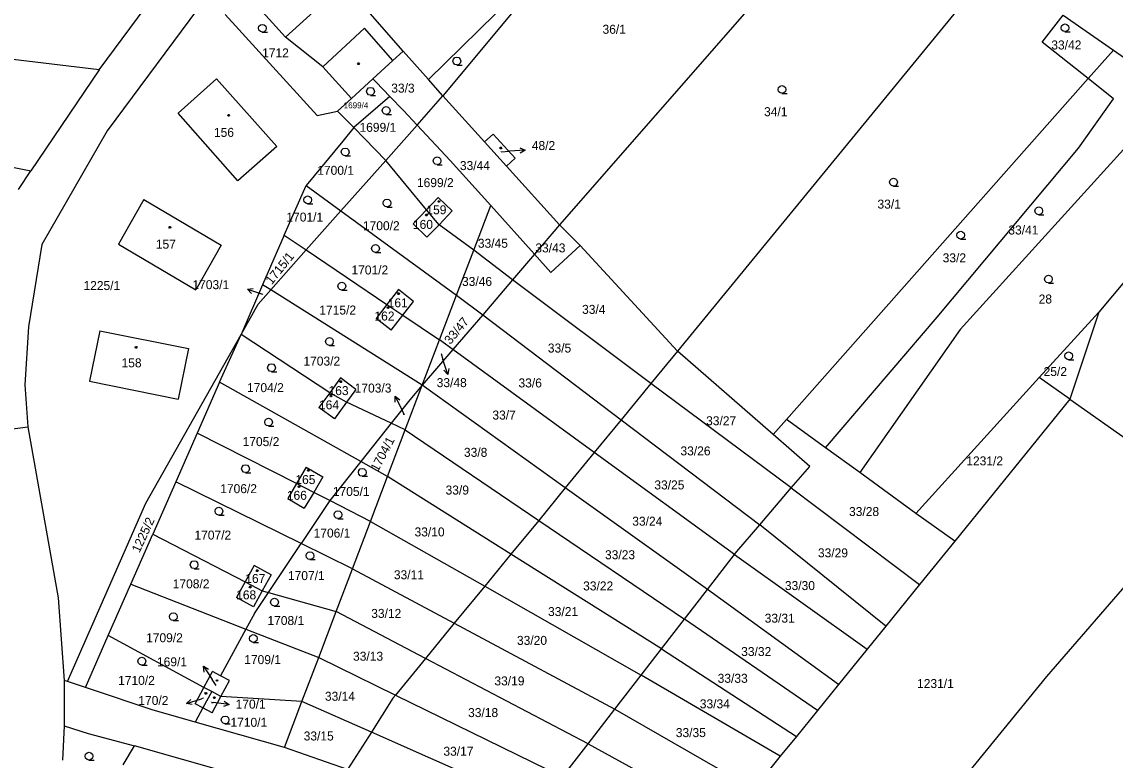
# Model space of a CAD drawing. Extents: x -802857 to -799647, y -1020285 to -1015884.
# Drawn here: x -801708.7 to -801501.8, y -1017921.9 to -1017782.1 of the extents above; entities that cross this region are included whole.
import ezdxf

# ---------------------------------------------------------------- set-up
doc = ezdxf.new("R2010")
doc.units = 0
for name, color, linetype in [('Default', 7, 'Continuous'), ('KN_HRANICE', 7, 'Continuous'), ('KN_KULTURY', 7, 'Continuous'), ('KN_PARCELY', 7, 'Continuous'), ('KN_SLUCKY', 7, 'Continuous')]:
    doc.layers.add(name, color=color, linetype=linetype)

# ---------------------------------------------------------------- blocks, each defined once
blk = doc.blocks.new('304')
at = {"layer": 'Default'}
blk.add_lwpolyline([(0, 0), (-0.38, 0.1), (-0.65, 0.37), (-0.75, 0.74), (-0.65, 1.11), (-0.38, 1.38), (-0.01, 1.48), (0.36, 1.38), (0.63, 1.11), (0.73, 0.73), (0.63, 0.35), (0.36, 0.08), (-0.02, -0.02), (0.98, -0.02)], dxfattribs=at)
blk = doc.blocks.new('10292')
at = {"layer": 'Default'}
blk.add_line((0, 3), (0, 0), dxfattribs=at)
blk.add_lwpolyline([(-0.5, 2), (0, 3), (0.5, 2)], dxfattribs=at)
blk = doc.blocks.new('402')
at = {"layer": 'Default'}
blk.add_lwpolyline([(0.09, 0.15), (0.18, 0), (0.09, -0.15), (-0.09, -0.15), (-0.18, 0), (-0.09, 0.15), (0.09, 0.15)], dxfattribs=at)

msp = doc.modelspace()

# ---------------------------------------------------------------- linework, layer by layer
at = {"layer": 'KN_HRANICE'}
for p, q in [((-801587.49, -1017746.18), (-801629.02, -1017796.14)), ((-801636.53, -1017787.69), (-801656.2, -1017765.17)), ((-801665.9, -1017766.77), (-801692.56, -1017802.78)), ((-801606.88, -1017768.59), (-801631.76, -1017793.06)), ((-801560.55, -1017767.41), (-801606.93, -1017820.56)), ((-801694.1, -1017791.18), (-801681, -1017773.54)), ((-801526.7, -1017773.73), (-801584.65, -1017844.45)), ((-801658.84, -1017785), (-801667.4, -1017775.47)), ((-801670.22, -1017780.7), (-801652.82, -1017799.83)), ((-801515.62, -1017785.98), (-801511.62, -1017780.82)), ((-801511.62, -1017780.82), (-801502.15, -1017787.45)), ((-801651.72, -1017790.61), (-801658.84, -1017785)), ((-801506.94, -1017792.87), (-801515.62, -1017785.98)), ((-801694.1, -1017791.18), (-801711.96, -1017789.03)), ((-801636.53, -1017787.69), (-801638.49, -1017789.43)), ((-801631.76, -1017793.06), (-801636.53, -1017787.69)), ((-801506.94, -1017792.87), (-801502.15, -1017787.45)), ((-801502.15, -1017787.45), (-801490.56, -1017795.57)), ((-801694.1, -1017791.18), (-801707.01, -1017810.3)), ((-801651.72, -1017790.61), (-801646.32, -1017796.61)), ((-801638.49, -1017789.43), (-801642.29, -1017792.91)), ((-801679.14, -1017799.41), (-801671.86, -1017792.92)), ((-801671.86, -1017792.92), (-801660.48, -1017805.72)), ((-801642.29, -1017792.91), (-801646.32, -1017796.61)), ((-801641.68, -1017793.54), (-801642.29, -1017792.91)), ((-801629.02, -1017796.14), (-801631.76, -1017793.06)), ((-801563.98, -1017857.43), (-801506.94, -1017792.87)), ((-801502.12, -1017796.69), (-801506.94, -1017792.87)), ((-801641.68, -1017793.54), (-801639.09, -1017796.22)), ((-801531.17, -1017840.39), (-801490.56, -1017795.57)), ((-801646.32, -1017796.61), (-801648.95, -1017799.02)), ((-801639.09, -1017796.22), (-801645.9, -1017802.13)), ((-801639.09, -1017796.22), (-801636.48, -1017798.92)), ((-801633.91, -1017801.66), (-801629.02, -1017796.14)), ((-801629.02, -1017796.14), (-801621.14, -1017804.85)), ((-801508.75, -1017806.02), (-801502.12, -1017796.69)), ((-801667.86, -1017812.23), (-801679.14, -1017799.41)), ((-801652.82, -1017799.83), (-801648.95, -1017799.02)), ((-801645.9, -1017802.13), (-801648.95, -1017799.02)), ((-801636.48, -1017798.92), (-801633.91, -1017801.66)), ((-801754.22, -1017801.07), (-801707.01, -1017810.3)), ((-801639.83, -1017808.34), (-801633.91, -1017801.66)), ((-801633.91, -1017801.66), (-801627.63, -1017808.36)), ((-801692.56, -1017802.78), (-801704.91, -1017824.25)), ((-801645.9, -1017802.13), (-801647.97, -1017804.68)), ((-801645.9, -1017802.13), (-801639.83, -1017808.34)), ((-801621.14, -1017804.85), (-801619.52, -1017803.38)), ((-801619.52, -1017803.38), (-801615.33, -1017807.93)), ((-801660.48, -1017805.72), (-801667.86, -1017812.23)), ((-801647.97, -1017804.68), (-801654.93, -1017813.11)), ((-801621.14, -1017804.85), (-801616.99, -1017809.44)), ((-801477.67, -1017804.6), (-801504.93, -1017837.07)), ((-801616.99, -1017809.44), (-801615.33, -1017807.93)), ((-801535.49, -1017838.02), (-801508.75, -1017806.02)), ((-801648.32, -1017817.92), (-801639.83, -1017808.34)), ((-801632.1, -1017817.7), (-801639.83, -1017808.34)), ((-801627.63, -1017808.36), (-801619.98, -1017816.88)), ((-801616.99, -1017809.44), (-801606.93, -1017820.56)), ((-801709.32, -1017813.86), (-801707.01, -1017810.3)), ((-801659.05, -1017822.48), (-801654.93, -1017813.11)), ((-801654.93, -1017813.11), (-801648.32, -1017817.92)), ((-801685.6, -1017815.77), (-801690.43, -1017824.24)), ((-801685.6, -1017815.77), (-801670.98, -1017824.37)), ((-801632.1, -1017817.7), (-801629.89, -1017815.39)), ((-801627.26, -1017817.92), (-801629.89, -1017815.39)), ((-801654.87, -1017825.31), (-801648.32, -1017817.92)), ((-801648.32, -1017817.92), (-801626.43, -1017833.85)), ((-801634.67, -1017820.37), (-801632.1, -1017817.7)), ((-801629.76, -1017820.53), (-801632.1, -1017817.7)), ((-801627.26, -1017817.92), (-801629.76, -1017820.53)), ((-801623.2, -1017825.34), (-801619.98, -1017816.88)), ((-801619.98, -1017816.88), (-801611.69, -1017826.12)), ((-801632.04, -1017822.9), (-801634.67, -1017820.37)), ((-801629.76, -1017820.53), (-801632.04, -1017822.9)), ((-801623.2, -1017825.34), (-801629.76, -1017820.53)), ((-801606.93, -1017820.56), (-801611.69, -1017826.12)), ((-801603.03, -1017824.46), (-801606.93, -1017820.56)), ((-801704.91, -1017824.25), (-801707.43, -1017839.85)), ((-801690.43, -1017824.24), (-801675.81, -1017832.84)), ((-801670.98, -1017824.37), (-801675.81, -1017832.84)), ((-801659.05, -1017822.48), (-801663.18, -1017831.89)), ((-801659.05, -1017822.48), (-801654.87, -1017825.31)), ((-801608.61, -1017829.56), (-801603.03, -1017824.46)), ((-801603.03, -1017824.46), (-801584.65, -1017844.45)), ((-801661.59, -1017832.89), (-801654.87, -1017825.31)), ((-801654.87, -1017825.31), (-801639.62, -1017835.62)), ((-801626.43, -1017833.85), (-801623.2, -1017825.34)), ((-801615.84, -1017830.97), (-801623.2, -1017825.34)), ((-801611.69, -1017826.12), (-801615.84, -1017830.97)), ((-801611.69, -1017826.12), (-801608.61, -1017829.56)), ((-801663.18, -1017831.89), (-801667.22, -1017841.33)), ((-801661.59, -1017832.89), (-801663.18, -1017831.89)), ((-801637.45, -1017832.82), (-801639.62, -1017835.62)), ((-801634.57, -1017835.06), (-801637.45, -1017832.82)), ((-801615.84, -1017830.97), (-801621.5, -1017837.59)), ((-801589.67, -1017850.59), (-801615.84, -1017830.97)), ((-801663.99, -1017835.6), (-801661.59, -1017832.89)), ((-801632.93, -1017850.94), (-801661.59, -1017832.89)), ((-801629.66, -1017842.35), (-801626.43, -1017833.85)), ((-801626.43, -1017833.85), (-801621.5, -1017837.59)), ((-801667.22, -1017841.33), (-801663.99, -1017835.6)), ((-801639.62, -1017835.62), (-801641.68, -1017838.27)), ((-801639.62, -1017835.62), (-801636.59, -1017837.67)), ((-801636.59, -1017837.67), (-801634.57, -1017835.06)), ((-801638.8, -1017840.51), (-801641.68, -1017838.27)), ((-801638.8, -1017840.51), (-801636.59, -1017837.67)), ((-801636.59, -1017837.67), (-801629.66, -1017842.35)), ((-801621.5, -1017837.59), (-801627.15, -1017844.18)), ((-801621.5, -1017837.59), (-801595.3, -1017857.46)), ((-801556.62, -1017862.76), (-801535.49, -1017838.02)), ((-801504.93, -1017837.07), (-801516.16, -1017849.45)), ((-801504.93, -1017837.07), (-801510.41, -1017853.59)), ((-801707.43, -1017839.85), (-801708.15, -1017850.85)), ((-801693.95, -1017840.61), (-801695.91, -1017850.17)), ((-801693.95, -1017840.61), (-801677.18, -1017843.99)), ((-801531.17, -1017840.39), (-801550.13, -1017867.47)), ((-801685.23, -1017873.24), (-801667.22, -1017841.33)), ((-801671.28, -1017850.32), (-801667.22, -1017841.33)), ((-801650.45, -1017852.35), (-801667.22, -1017841.33)), ((-801632.93, -1017850.94), (-801629.66, -1017842.35)), ((-801627.15, -1017844.18), (-801629.66, -1017842.35)), ((-801677.18, -1017843.99), (-801679.14, -1017853.55)), ((-801627.15, -1017844.18), (-801632.93, -1017850.94)), ((-801600.38, -1017863.66), (-801627.15, -1017844.18)), ((-801584.65, -1017844.45), (-801589.67, -1017850.59)), ((-801566.54, -1017860.25), (-801584.65, -1017844.45)), ((-801708.15, -1017850.85), (-801707.54, -1017858.79)), ((-801695.91, -1017850.17), (-801679.14, -1017853.55)), ((-801671.28, -1017850.32), (-801675.52, -1017859.98)), ((-801644.53, -1017865.36), (-801671.28, -1017850.32)), ((-801648.43, -1017849.55), (-801650.45, -1017852.35)), ((-801645.48, -1017851.7), (-801648.43, -1017849.55)), ((-801636.14, -1017859.39), (-801632.93, -1017850.94)), ((-801632.93, -1017850.94), (-801635.29, -1017853.7)), ((-801605.86, -1017870.35), (-801632.93, -1017850.94)), ((-801589.67, -1017850.59), (-801595.3, -1017857.46)), ((-801563.11, -1017870.36), (-801589.67, -1017850.59)), ((-801516.16, -1017849.45), (-801539.5, -1017875.18)), ((-801510.41, -1017853.59), (-801516.16, -1017849.45)), ((-801650.45, -1017852.35), (-801652.49, -1017855.13)), ((-801647.25, -1017854.13), (-801650.45, -1017852.35)), ((-801645.48, -1017851.7), (-801647.25, -1017854.13)), ((-801649.54, -1017857.28), (-801652.49, -1017855.13)), ((-801647.25, -1017854.13), (-801649.54, -1017857.28)), ((-801638.8, -1017858.13), (-801647.25, -1017854.13)), ((-801635.29, -1017853.7), (-801638.8, -1017858.13)), ((-801510.41, -1017853.59), (-801532.16, -1017880.43)), ((-801510.41, -1017853.59), (-801498.22, -1017862.16)), ((-801595.3, -1017857.46), (-801600.38, -1017863.66)), ((-801595.3, -1017857.46), (-801569.08, -1017877.35)), ((-801563.98, -1017857.43), (-801566.54, -1017860.25)), ((-801556.62, -1017862.76), (-801563.98, -1017857.43)), ((-801717.29, -1017860.13), (-801707.54, -1017858.79)), ((-801707.54, -1017858.79), (-801701.82, -1017891.2)), ((-801638.8, -1017858.13), (-801644.53, -1017865.36)), ((-801639.49, -1017868.19), (-801636.14, -1017859.39)), ((-801636.14, -1017859.39), (-801638.8, -1017858.13)), ((-801636.14, -1017859.39), (-801610.9, -1017876.51)), ((-801675.52, -1017859.98), (-801679.59, -1017869.24)), ((-801656.73, -1017869.56), (-801675.52, -1017859.98)), ((-801559.61, -1017866.3), (-801566.54, -1017860.25)), ((-801600.38, -1017863.66), (-801605.86, -1017870.35)), ((-801573.84, -1017882.97), (-801600.38, -1017863.66)), ((-801550.13, -1017867.47), (-801556.62, -1017862.76)), ((-801644.53, -1017865.36), (-801650.41, -1017872.78)), ((-801639.49, -1017868.19), (-801644.53, -1017865.36)), ((-801654.89, -1017866.43), (-801656.73, -1017869.56)), ((-801654.89, -1017866.43), (-801651.74, -1017868.29)), ((-801563.11, -1017870.36), (-801559.61, -1017866.3)), ((-801539.5, -1017875.18), (-801550.13, -1017867.47)), ((-801679.59, -1017869.24), (-801683.94, -1017879.14)), ((-801655.86, -1017880.92), (-801679.59, -1017869.24)), ((-801656.73, -1017869.56), (-801658.39, -1017872.37)), ((-801653.47, -1017871.22), (-801656.73, -1017869.56)), ((-801651.74, -1017868.29), (-801653.47, -1017871.22)), ((-801642.73, -1017876.71), (-801639.49, -1017868.19)), ((-801616.14, -1017882.9), (-801639.49, -1017868.19)), ((-801514.75, -1017906.05), (-801482.86, -1017869.28)), ((-801653.47, -1017871.22), (-801655.25, -1017874.23)), ((-801650.41, -1017872.78), (-801653.47, -1017871.22)), ((-801605.86, -1017870.35), (-801610.9, -1017876.51)), ((-801578.98, -1017889.62), (-801605.86, -1017870.35)), ((-801569.08, -1017877.35), (-801563.11, -1017870.36)), ((-801563.11, -1017870.36), (-801538.82, -1017888.65)), ((-801700.05, -1017907.03), (-801685.23, -1017873.24)), ((-801658.39, -1017872.37), (-801655.25, -1017874.23)), ((-801650.41, -1017872.78), (-801655.86, -1017880.92)), ((-801642.73, -1017876.71), (-801650.41, -1017872.78)), ((-801532.16, -1017880.43), (-801539.5, -1017875.18)), ((-801646.15, -1017885.7), (-801642.73, -1017876.71)), ((-801642.73, -1017876.71), (-801621.12, -1017888.98)), ((-801610.9, -1017876.51), (-801616.14, -1017882.9)), ((-801610.9, -1017876.51), (-801583.31, -1017895.22)), ((-801573.38, -1017882.38), (-801569.08, -1017877.35)), ((-801545.21, -1017896.54), (-801569.08, -1017877.35)), ((-801688.1, -1017888.6), (-801683.94, -1017879.14)), ((-801683.94, -1017879.14), (-801666.46, -1017888.17)), ((-801662.05, -1017890.18), (-801655.86, -1017880.92)), ((-801646.15, -1017885.7), (-801655.86, -1017880.92)), ((-801573.84, -1017882.97), (-801573.38, -1017882.38)), ((-801532.16, -1017880.43), (-801538.82, -1017888.65)), ((-801616.14, -1017882.9), (-801621.12, -1017888.98)), ((-801587.67, -1017900.85), (-801616.14, -1017882.9)), ((-801578.98, -1017889.62), (-801573.84, -1017882.97)), ((-801573.84, -1017882.97), (-801548.75, -1017900.91)), ((-801664.73, -1017885.06), (-801666.46, -1017888.17)), ((-801661.54, -1017886.83), (-801664.73, -1017885.06)), ((-801649.21, -1017893.75), (-801646.15, -1017885.7)), ((-801646.15, -1017885.7), (-801626.87, -1017896)), ((-801692.35, -1017898.29), (-801688.1, -1017888.6)), ((-801688.1, -1017888.6), (-801666.31, -1017897.09)), ((-801666.46, -1017888.17), (-801668.08, -1017891.09)), ((-801666.46, -1017888.17), (-801663.22, -1017889.85)), ((-801661.54, -1017886.83), (-801663.22, -1017889.85)), ((-801538.82, -1017888.65), (-801545.21, -1017896.54)), ((-801663.22, -1017889.85), (-801664.89, -1017892.87)), ((-801664.7, -1017894.14), (-801662.05, -1017890.18)), ((-801663.22, -1017889.85), (-801662.05, -1017890.18)), ((-801662.05, -1017890.18), (-801649.21, -1017893.75)), ((-801621.12, -1017888.98), (-801626.87, -1017896)), ((-801621.12, -1017888.98), (-801591.49, -1017905.8)), ((-801583.31, -1017895.22), (-801578.98, -1017889.62)), ((-801554.19, -1017907.62), (-801578.98, -1017889.62)), ((-801701.82, -1017891.2), (-801700.72, -1017906.81)), ((-801664.89, -1017892.87), (-801668.08, -1017891.09)), ((-801664.7, -1017894.14), (-801666.31, -1017897.09)), ((-801652.52, -1017902.46), (-801649.21, -1017893.75)), ((-801632.31, -1017902.64), (-801649.21, -1017893.75)), ((-801626.87, -1017896), (-801632.31, -1017902.64)), ((-801626.87, -1017896), (-801596.46, -1017912.23)), ((-801587.67, -1017900.85), (-801583.31, -1017895.22)), ((-801558.14, -1017912.49), (-801583.31, -1017895.22)), ((-801545.21, -1017896.54), (-801548.75, -1017900.91)), ((-801696.68, -1017908.14), (-801692.35, -1017898.29)), ((-801674.24, -1017908.14), (-801692.35, -1017898.29)), ((-801666.31, -1017897.09), (-801671.13, -1017905.94)), ((-801666.31, -1017897.09), (-801652.52, -1017902.46)), ((-801591.49, -1017905.8), (-801587.67, -1017900.85)), ((-801587.67, -1017900.85), (-801562.14, -1017917.44)), ((-801548.75, -1017900.91), (-801554.19, -1017907.62)), ((-801655.69, -1017910.79), (-801652.52, -1017902.46)), ((-801652.52, -1017902.46), (-801638, -1017909.59)), ((-801632.31, -1017902.64), (-801638, -1017909.59)), ((-801601.56, -1017918.81), (-801632.31, -1017902.64)), ((-801674.24, -1017908.14), (-801672.63, -1017905.14)), ((-801671.13, -1017905.94), (-801672.63, -1017905.14)), ((-801700.72, -1017906.81), (-801700.71, -1017915.44)), ((-801700.05, -1017907.03), (-801700.72, -1017906.81)), ((-801696.68, -1017908.14), (-801700.05, -1017907.03)), ((-801669.41, -1017906.86), (-801671.13, -1017905.94)), ((-801671.02, -1017909.86), (-801669.41, -1017906.86)), ((-801596.46, -1017912.23), (-801591.49, -1017905.8)), ((-801565.18, -1017921.19), (-801591.49, -1017905.8)), ((-801545.79, -1017944.12), (-801514.75, -1017906.05)), ((-801695.73, -1017908.45), (-801696.68, -1017908.14)), ((-801684.06, -1017912.38), (-801695.73, -1017908.45)), ((-801675.89, -1017911.22), (-801674.24, -1017908.14)), ((-801672.76, -1017908.93), (-801674.43, -1017912)), ((-801672.76, -1017908.93), (-801674.24, -1017908.14)), ((-801671.02, -1017909.86), (-801672.76, -1017908.93)), ((-801554.19, -1017907.62), (-801558.14, -1017912.49)), ((-801674.43, -1017912), (-801675.89, -1017911.22)), ((-801672.67, -1017912.94), (-801671.02, -1017909.86)), ((-801655.69, -1017910.79), (-801671.02, -1017909.86)), ((-801659, -1017919.5), (-801655.69, -1017910.79)), ((-801642.56, -1017916.61), (-801655.69, -1017910.79)), ((-801638.47, -1017910.16), (-801642.56, -1017916.61)), ((-801638, -1017909.59), (-801638.47, -1017910.16)), ((-801638, -1017909.59), (-801606.41, -1017925.09)), ((-801675.91, -1017914.7), (-801684.06, -1017912.38)), ((-801674.43, -1017912), (-801675.91, -1017914.7)), ((-801672.67, -1017912.94), (-801674.43, -1017912)), ((-801601.56, -1017918.81), (-801596.46, -1017912.23)), ((-801596.46, -1017912.23), (-801570.17, -1017927.35)), ((-801558.14, -1017912.49), (-801562.14, -1017917.44)), ((-801700.71, -1017915.44), (-801701.04, -1017921.92)), ((-801700.71, -1017915.44), (-801696.14, -1017916.89)), ((-801659, -1017919.5), (-801675.91, -1017914.7)), ((-801696.14, -1017916.89), (-801687.37, -1017919.18)), ((-801642.56, -1017916.61), (-801647.06, -1017923.69)), ((-801610.75, -1017930.7), (-801642.56, -1017916.61)), ((-801562.14, -1017917.44), (-801565.18, -1017921.19)), ((-801689.53, -1017922.82), (-801687.37, -1017919.18)), ((-801669.21, -1017924.37), (-801687.37, -1017919.18)), ((-801647.06, -1017923.69), (-801659, -1017919.5)), ((-801606.41, -1017925.09), (-801601.56, -1017918.81)), ((-801601.56, -1017918.81), (-801575.03, -1017933.33)), ((-801565.18, -1017921.19), (-801570.17, -1017927.35))]:
    msp.add_line(p, q, dxfattribs=at)
at = {"layer": 'KN_PARCELY'}
for p, q in [((-801618.02, -1017806.73), (-801616.43, -1017806.61)), ((-801663.11, -1017833.73), (-801663.19, -1017833.7)), ((-801629.38, -1017844.9), (-801629.01, -1017846.02)), ((-801636.29, -1017856.55), (-801636.72, -1017855.7)), ((-801671.96, -1017907.81), (-801672.71, -1017906.66)), ((-801674.38, -1017910.21), (-801674.68, -1017910.3)), ((-801672.82, -1017910.97), (-801672.47, -1017911.01))]:
    msp.add_line(p, q, dxfattribs=at)
at = {"layer": 'KN_SLUCKY'}
for p, q in [((-801652.2, -1017779.01), (-801658.84, -1017785)), ((-801651.72, -1017790.61), (-801643.83, -1017783.33)), ((-801638.49, -1017789.43), (-801643.83, -1017783.33))]:
    msp.add_line(p, q, dxfattribs=at)

# ---------------------------------------------------------------- block references
at = {"layer": 'KN_KULTURY'}
for name, p in [('304', (-801663.19, -1017784.07)), ('304', (-801511.29, -1017783.97)), ('304', (-801626.37, -1017790.27)), ('402', (-801645, -1017790.03)), ('304', (-801642.73, -1017796.01)), ('304', (-801564.85, -1017795.65)), ('402', (-801669.57, -1017799.83)), ('304', (-801639.75, -1017799.64)), ('402', (-801618.08, -1017805.98)), ('304', (-801647.51, -1017807.49)), ('304', (-801630.12, -1017809.15)), ('304', (-801543.76, -1017813.22)), ('304', (-801654.61, -1017816.56)), ('304', (-801639.6, -1017817.16)), ('402', (-801629.79, -1017816.13)), ('304', (-801516.26, -1017818.64)), ('402', (-801632.15, -1017818.7)), ('402', (-801680.68, -1017821.01)), ('304', (-801531.03, -1017823.24)), ('304', (-801641.77, -1017825.76)), ('304', (-801514.43, -1017831.56)), ('304', (-801648.14, -1017832.9)), ('402', (-801637.41, -1017833.6)), ('402', (-801639.42, -1017836.22)), ('304', (-801650.49, -1017843.39)), ('402', (-801687.08, -1017843.76)), ('304', (-801510.6, -1017846.11)), ('304', (-801661.45, -1017848.34)), ('402', (-801648.35, -1017850.26)), ('402', (-801650.21, -1017852.98)), ('304', (-801662, -1017858.64)), ('304', (-801666.37, -1017867.47)), ('402', (-801654.48, -1017867.06)), ('304', (-801644.27, -1017868.15)), ('402', (-801656.25, -1017870.15)), ('304', (-801671.4, -1017875.52)), ('304', (-801648.87, -1017876.17)), ('304', (-801654.17, -1017883.93)), ('304', (-801676.1, -1017885.64)), ('402', (-801664.16, -1017886.03)), ('402', (-801665.49, -1017889.11)), ('304', (-801660.87, -1017892.74)), ('304', (-801680.03, -1017895.48)), ('304', (-801664.89, -1017899.62)), ('304', (-801686, -1017903.92)), ('402', (-801671.78, -1017906.84)), ('402', (-801673.88, -1017909.28)), ('402', (-801672.27, -1017910.09)), ('304', (-801670.24, -1017915.04)), ('304', (-801695.98, -1017921.89))]:
    msp.add_blockref(name, p, dxfattribs=at)
at = {"layer": 'KN_PARCELY'}
for p, rotation in [((-801616.43, -1017806.61), -85.78239900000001), ((-801663.19, -1017833.7), 71.104062), ((-801629.01, -1017846.02), -161.58471600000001), ((-801636.72, -1017855.7), 26.642537), ((-801672.71, -1017906.66), 33.231552), ((-801674.68, -1017910.3), 106.856629), ((-801672.47, -1017911.01), -96.840485)]:
    msp.add_blockref('10292', p, dxfattribs=dict(at, rotation=rotation))

# ---------------------------------------------------------------- texts
for s, height, p in [('36/1', 1.7, (-801598.82, -1017784.37)), ('1712', 1.7, (-801663.24, -1017788.85)), ('33/42', 1.7, (-801513.89, -1017787.34)), ('33/3', 1.7, (-801638.8, -1017795.51)), ('1699/4', 1.14, (-801647.8, -1017798.49)), ('34/1', 1.7, (-801568.25, -1017799.98)), ('1699/1', 1.7, (-801644.81, -1017802.94)), ('156', 1.7, (-801672.35, -1017803.89)), ('48/2', 1.7, (-801612.2, -1017806.39)), ('48/2', 0.1, (-801618.22, -1017806.73)), ('1700/1', 1.7, (-801652.8, -1017811.08)), ('33/44', 1.7, (-801625.81, -1017810.18)), ('1699/2', 1.7, (-801633.94, -1017813.41)), ('33/1', 1.7, (-801546.79, -1017817.48)), ('1701/1', 1.7, (-801658.64, -1017819.93)), ('159', 1.7, (-801632.15, -1017818.55)), ('1700/2', 1.7, (-801644.16, -1017821.57)), ('160', 1.7, (-801634.7, -1017821.32)), ('33/41', 1.7, (-801522.02, -1017822.38)), ('157', 1.7, (-801683.35, -1017825.07)), ('33/45', 1.7, (-801622.41, -1017824.89)), ('33/43', 1.7, (-801611.53, -1017825.77)), ('33/2', 1.7, (-801534.45, -1017827.65)), ('1701/2', 1.7, (-801646.33, -1017829.95)), ('33/46', 1.7, (-801625.41, -1017832.12)), ('1225/1', 1.7, (-801697.04, -1017832.9)), ('1703/1', 1.7, (-801676.42, -1017832.73)), ('1703/1', 0.1, (-801663.39, -1017833.73)), ('161', 1.7, (-801639.47, -1017836.16)), ('28', 1.7, (-801516.29, -1017835.45)), ('1715/2', 1.7, (-801652.41, -1017837.53)), ('162', 1.7, (-801641.98, -1017838.67)), ('33/4', 1.7, (-801602.69, -1017837.41)), ('33/5', 1.7, (-801609.17, -1017844.73)), ('33/48', 0.1, (-801629.62, -1017844.9)), ('158', 1.7, (-801689.84, -1017847.53)), ('1703/2', 1.7, (-801655.42, -1017847.2)), ('25/2', 1.7, (-801515.35, -1017849.18)), ('1704/2', 1.7, (-801666.09, -1017852.23)), ('163', 1.7, (-801650.67, -1017852.79)), ('1703/3', 1.7, (-801645.72, -1017852.31)), ('33/48', 1.7, (-801630.2, -1017851.28)), ('33/6', 1.7, (-801614.72, -1017851.34)), ('164', 1.7, (-801652.47, -1017855.49)), ('1703/3', 0.1, (-801636.59, -1017856.55)), ('33/7', 1.7, (-801619.66, -1017857.42)), ('33/27', 1.7, (-801579.22, -1017858.5)), ('1705/2', 1.7, (-801666.93, -1017862.45)), ('33/8', 1.7, (-801625.04, -1017864.48)), ('33/26', 1.7, (-801584.07, -1017864.21)), ('1231/2', 1.7, (-801529.98, -1017866.1)), ('165', 1.7, (-801656.94, -1017869.64)), ('1706/2', 1.7, (-801671.16, -1017871.36)), ('33/9', 1.7, (-801628.52, -1017871.62)), ('33/25', 1.7, (-801589.01, -1017870.65)), ('166', 1.7, (-801658.56, -1017872.62)), ('1705/1', 1.7, (-801649.85, -1017871.89)), ('33/28', 1.7, (-801552.17, -1017875.69)), ('33/24', 1.7, (-801593.19, -1017877.52)), ('1706/1', 1.7, (-801653.49, -1017879.76)), ('33/10', 1.7, (-801634.39, -1017879.55)), ('1707/2', 1.7, (-801676.04, -1017880.15)), ('33/23', 1.7, (-801598.35, -1017883.87)), ('33/29', 1.7, (-801558.06, -1017883.51)), ('1707/1', 1.7, (-801658.35, -1017887.82)), ('33/11', 1.7, (-801638.3, -1017887.66)), ('1708/2', 1.7, (-801680.15, -1017889.38)), ('167', 1.7, (-801666.42, -1017888.36)), ('33/22', 1.7, (-801602.49, -1017889.78)), ('33/30', 1.7, (-801564.31, -1017889.71)), ('168', 1.7, (-801668.15, -1017891.47)), ('1708/1', 1.7, (-801662.23, -1017896.33)), ('33/12', 1.7, (-801642.59, -1017894.98)), ('33/21', 1.7, (-801609.13, -1017894.63)), ('33/31', 1.7, (-801568.13, -1017895.88)), ('1709/2', 1.7, (-801685.19, -1017899.59)), ('33/20', 1.7, (-801615.01, -1017900.09)), ('33/32', 1.7, (-801572.58, -1017902.2)), ('169/1', 1.7, (-801683.13, -1017904.15)), ('1709/1', 1.7, (-801666.62, -1017903.73)), ('33/13', 1.7, (-801646.03, -1017903.09)), ('1710/2', 1.7, (-801690.49, -1017907.66)), ('33/19', 1.7, (-801619.28, -1017907.76)), ('33/33', 1.7, (-801577.03, -1017907.27)), ('1231/1', 1.7, (-801539.3, -1017908.26)), ('169/1', 0.1, (-801672.2, -1017907.81)), ('33/14', 1.7, (-801651.35, -1017910.67)), ('170/2', 1.7, (-801686.66, -1017911.46)), ('170/2', 0.1, (-801674.63, -1017910.21)), ('170/1', 0.1, (-801673.06, -1017910.97)), ('170/1', 1.7, (-801668.25, -1017912.16)), ('33/34', 1.7, (-801580.41, -1017912.1)), ('33/18', 1.7, (-801624.26, -1017913.76)), ('1710/1', 1.7, (-801669.23, -1017915.6)), ('33/15', 1.7, (-801655.37, -1017918.19)), ('33/35', 1.7, (-801584.95, -1017917.55)), ('33/17', 1.7, (-801628.93, -1017921.08))]:
    msp.add_text(s, height=height, dxfattribs=at).set_placement(p)
for s, rotation, p in [('1715/1', 51.28, (-801661.41, -1017832)), ('33/47', 50.306, (-801627.62, -1017843.32)), ('1704/1', 62.281, (-801641.32, -1017867.42)), ('1225/2', 65.145, (-801686.45, -1017882.76))]:
    msp.add_text(s, height=1.7, rotation=rotation, dxfattribs=at).set_placement(p)

doc.saveas('drawing.dxf')
